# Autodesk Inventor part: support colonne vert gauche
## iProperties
Shininess: 64.0
Length Units: 11269
Angle Units: 11279
Time Units: 11290
Mass Units: 11283
Length Display Precision: 3
Angle Display Precision: 2
Compacted: True
Part Number: support colonne vert gauche
Document SubType Name: Modeling
Created: 2005-01
Material: Par défaut
Designer: LEGERET Philippe
Density: 0.0
Volumn: 0.0
Area: 0.0
PropertySet Name: Model Information
Control State: 0
Master: False
Checked Out: False
Author: LEGERET Philippe
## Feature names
1. Extrusion1
2. Perçage1 [Hole]
3. Perçage2 [Hole]
4. Chanfrein1 [Chamfer]
5. Chanfrein2 [Chamfer]
6. Chanfrein3 [Chamfer]
